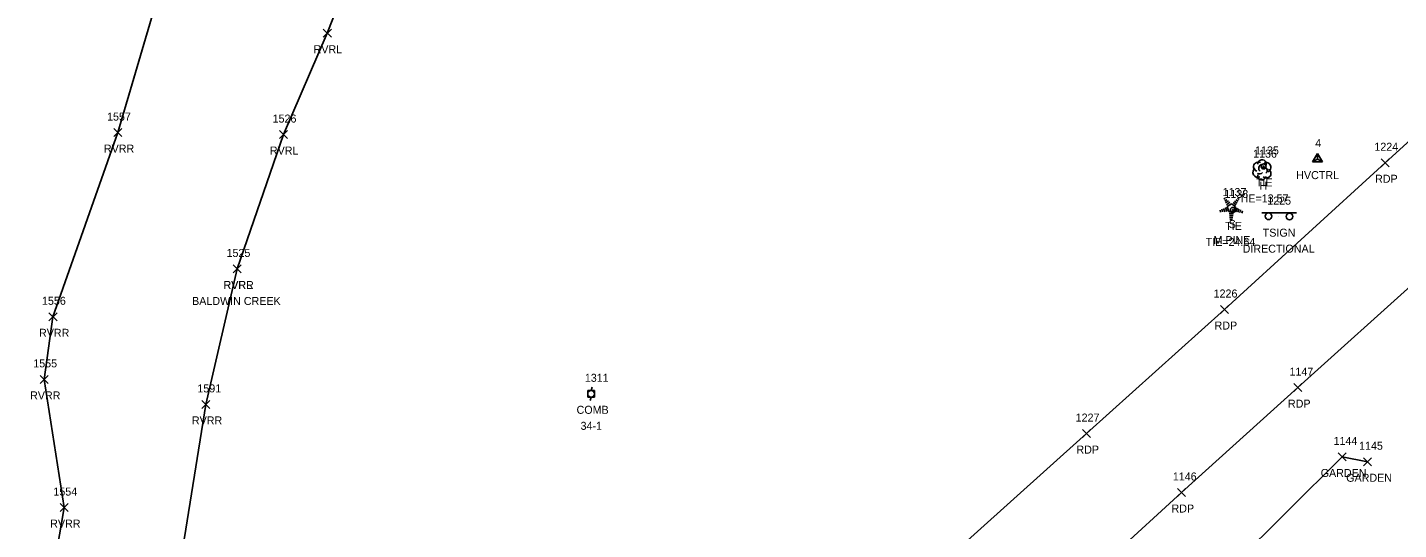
# Model space of a CAD drawing. Extents: x 1496556 to 1498241, y 599216 to 604470.
# Drawn here: x 1497204.8 to 1497547.4, y 603168.8 to 603294.3 of the extents above; entities that cross this region are included whole.
import ezdxf

# ---------------------------------------------------------------- set-up
doc = ezdxf.new("R2010")
doc.units = 0
for name, color, linetype in [('C_A', 7, 'Continuous'), ('C_C', 7, 'Continuous'), ('C_I', 7, 'Continuous'), ('CBP', 7, 'Continuous'), ('CPSM', 7, 'Continuous'), ('L_A', 7, 'Continuous'), ('L_C', 7, 'Continuous'), ('L_I', 7, 'Continuous'), ('L_TIC', 7, 'Continuous'), ('LAPB', 7, 'Continuous'), ('LAWE', 7, 'Continuous'), ('LTC', 7, 'Continuous'), ('LTD', 7, 'Continuous'), ('P_A', 7, 'Continuous'), ('P_I', 7, 'Continuous'), ('P_TIC', 7, 'Continuous'), ('PET', 7, 'Continuous'), ('S_A', 7, 'Continuous'), ('S_C', 7, 'Continuous'), ('S_I', 7, 'Continuous'), ('SSGN', 7, 'Continuous'), ('U_A', 7, 'Continuous'), ('U_C', 7, 'Continuous'), ('U_I', 7, 'Continuous'), ('UP', 7, 'Continuous')]:
    doc.layers.add(name, color=color, linetype=linetype)

msp = doc.modelspace()

# ---------------------------------------------------------------- linework, layer by layer
at = {"layer": 'CBP'}
for centre, radius in [((1497513.71, 603259.59), 0.625), ((1497513.71, 603259.59), 0.0833), ((1497506.03, 603248.72), 0.625), ((1497506.03, 603248.72), 0.0833)]:
    msp.add_circle(centre, radius, dxfattribs=at)
at = {"layer": 'CPSM'}
for p, q in [((1497525.91, 603260.69), (1497527.16, 603262.85)), ((1497525.91, 603260.69), (1497527.16, 603261.41)), ((1497528.41, 603260.69), (1497527.16, 603262.85)), ((1497527.16, 603261.41), (1497527.16, 603262.85)), ((1497527.16, 603261.41), (1497527.16, 603261.41)), ((1497527.16, 603261.41), (1497528.41, 603260.69)), ((1497525.91, 603260.69), (1497528.41, 603260.69))]:
    msp.add_line(p, q, dxfattribs=at)
at = {"layer": 'L_TIC'}
for points in [[(1497278.78, 603291.86), (1497280.78, 603293.86)], [(1497280.78, 603291.86), (1497278.78, 603293.86)], [(1497226.45, 603267.03), (1497228.45, 603269.03)], [(1497228.45, 603267.03), (1497226.45, 603269.03)], [(1497267.86, 603266.54), (1497269.86, 603268.54)], [(1497269.86, 603266.54), (1497267.86, 603268.54)], [(1497256.29, 603232.96), (1497258.29, 603234.96)], [(1497258.29, 603232.96), (1497256.29, 603234.96)], [(1497256.29, 603232.96), (1497258.29, 603234.96)], [(1497258.29, 603232.96), (1497256.29, 603234.96)], [(1497210.24, 603221.01), (1497212.24, 603223.01)], [(1497212.24, 603221.01), (1497210.24, 603223.01)], [(1497208.01, 603205.37), (1497210.01, 603207.37)], [(1497210.01, 603205.37), (1497208.01, 603207.37)], [(1497248.44, 603199.12), (1497250.44, 603201.12)], [(1497250.44, 603199.12), (1497248.44, 603201.12)], [(1497532.3, 603185.99), (1497534.3, 603187.99)], [(1497534.3, 603185.99), (1497532.3, 603187.99)], [(1497538.67, 603184.79), (1497540.67, 603186.79)], [(1497540.67, 603184.79), (1497538.67, 603186.79)], [(1497213.03, 603173.34), (1497215.03, 603175.34)], [(1497215.03, 603173.34), (1497213.03, 603175.34)]]:
    msp.add_lwpolyline(points, dxfattribs=at)
at = {"layer": 'LAPB'}
msp.add_lwpolyline([(1497506.31, 603145.06), (1497502.6, 603154.88), (1497506.17, 603160.03), (1497533.3, 603186.99), (1497539.67, 603185.79)], dxfattribs=at)
at = {"layer": 'LAWE'}
for points in [[(1497189.81, 603091.49), (1497191.67, 603112.98), (1497209.98, 603150.46), (1497214.03, 603174.34), (1497209.01, 603206.37), (1497211.24, 603222.01), (1497227.45, 603268.03), (1497246.38, 603332.34), (1497269.89, 603360.04), (1497296.95, 603397.6), (1497313.57, 603422.44), (1497323.64, 603438.94), (1497334.8, 603445.38), (1497344.77, 603450.19), (1497370.1, 603467.8), (1497419.49, 603471.31), (1497456.04, 603468.84), (1497488.04, 603460.85), (1497518.38, 603461.84), (1497564.45, 603467.31)], [(1497257.29, 603233.96), (1497268.86, 603267.54), (1497279.78, 603292.86), (1497288.82, 603315.96), (1497298.59, 603335.95), (1497306.16, 603346.61), (1497313.39, 603358.86), (1497323.23, 603375.14), (1497334.35, 603385.12), (1497348.33, 603402.71), (1497361.35, 603417.11), (1497378.91, 603425.6), (1497400.91, 603427.88), (1497444.15, 603428.7), (1497481.24, 603420.82), (1497519.31, 603418.69), (1497550.81, 603423.71)], [(1497257.29, 603233.96), (1497249.44, 603200.12), (1497237.58, 603126.42), (1497229.71, 603101.35), (1497207.4, 603061.16)]]:
    msp.add_lwpolyline(points, dxfattribs=at)
at = {"layer": 'LTC'}
for p, q in [((1497503.78, 603251.38), (1497504.13, 603251.64)), ((1497503.98, 603250.92), (1497504.51, 603251.3)), ((1497504.19, 603250.45), (1497504.9, 603250.96)), ((1497506.43, 603250.93), (1497507.11, 603250.43)), ((1497506.8, 603251.27), (1497507.35, 603250.87)), ((1497507.17, 603251.62), (1497507.59, 603251.32)), ((1497502.81, 603248.66), (1497502.96, 603248.19)), ((1497503.26, 603248.88), (1497503.47, 603248.23)), ((1497503.72, 603249.09), (1497503.99, 603248.26)), ((1497504.17, 603249.31), (1497504.5, 603248.29)), ((1497504.4, 603249.98), (1497505.28, 603250.62)), ((1497504.63, 603249.53), (1497505.64, 603250.26)), ((1497504.63, 603249.53), (1497505.02, 603248.34)), ((1497506.25, 603248.34), (1497505.02, 603248.34)), ((1497506.21, 603247.84), (1497505.06, 603247.84)), ((1497506.12, 603247.34), (1497505.14, 603247.34)), ((1497505.64, 603250.26), (1497506.64, 603249.54)), ((1497506.06, 603250.58), (1497506.87, 603249.99)), ((1497506.64, 603249.54), (1497506.25, 603248.34)), ((1497507.07, 603249.27), (1497506.74, 603248.23)), ((1497507.52, 603249.02), (1497507.23, 603248.13)), ((1497507.96, 603248.77), (1497507.73, 603248.04)), ((1497508.41, 603248.52), (1497508.22, 603247.94)), ((1497506.04, 603246.84), (1497505.21, 603246.84)), ((1497505.96, 603246.34), (1497505.28, 603246.34))]:
    msp.add_line(p, q, dxfattribs=at)
at = {"layer": 'LTD'}
msp.add_line((1497513.26, 603258.77), (1497513.26, 603258.77), dxfattribs=at)
msp.add_line((1497513.26, 603258.77), (1497513.26, 603258.77), dxfattribs=at)
msp.add_arc((1497513.3, 603260.2), 1.05, 335.5272, 180.9563, dxfattribs=at)
for centre, major_axis, ratio, start_param, end_param in [((1497512.17, 603258.06), (0.58, -1.04), 0.959034, 3.141593, 6.283185), ((1497512.47, 603259.44), (1.21, -0.51), 0.895232, 1.570796, 4.712389), ((1497512.8, 603258.02), (-0.625, -0.083), 0.423636, 0, 3.141593), ((1497513.05, 603259.23), (-0.208, -0.792), 0.645439, 3.141593, 6.283185), ((1497513.76, 603258.6), (-0.5, 0.667), 0.989748, 3.141593, 6.283185), ((1497514.26, 603257.94), (-1.09, 0.79), 0.841452, 1.570796, 4.712389), ((1497514.3, 603259.35), (-1.14, -0.48), 0.949671, 1.570796, 4.712389), ((1497513.26, 603257.27), (0.26, 1.06), 0.942809, 1.570796, 4.712389)]:
    msp.add_ellipse(centre, major_axis=major_axis, ratio=ratio, start_param=start_param, end_param=end_param, dxfattribs=at)
at = {"layer": 'P_TIC'}
for points in [[(1497543.07, 603259.5), (1497545.07, 603261.5)], [(1497545.07, 603259.5), (1497543.07, 603261.5)], [(1497502.96, 603222.83), (1497504.96, 603224.83)], [(1497504.96, 603222.83), (1497502.96, 603224.83)], [(1497521.29, 603203.31), (1497523.29, 603205.31)], [(1497523.29, 603203.31), (1497521.29, 603205.31)], [(1497468.44, 603191.83), (1497470.44, 603193.83)], [(1497470.44, 603191.83), (1497468.44, 603193.83)], [(1497492.2, 603177.11), (1497494.2, 603179.11)], [(1497494.2, 603177.11), (1497492.2, 603179.11)]]:
    msp.add_lwpolyline(points, dxfattribs=at)
at = {"layer": 'PET'}
for points in [[(1497580.33, 603293.36), (1497544.07, 603260.5), (1497503.96, 603223.83), (1497469.44, 603192.83), (1497432.27, 603159.48), (1497398.1, 603128.8), (1497361.66, 603094.11), (1497332.15, 603067.83), (1497309.09, 603046.17), (1497294.72, 603034.46), (1497285.78, 603029.77), (1497276.79, 603028.23), (1497267.28, 603029.35), (1497255.38, 603035.01), (1497245.34, 603044.47)], [(1497277.08, 602932.51), (1497278.76, 602955.27), (1497283.83, 602972.38), (1497292.85, 602989.5), (1497302.51, 603001.53), (1497319.84, 603019.72), (1497338.13, 603037.05), (1497360.02, 603057.19), (1497386.8, 603081.38), (1497411.61, 603104.29), (1497436.99, 603126.72), (1497459.34, 603147.15), (1497493.2, 603178.11), (1497522.29, 603204.31), (1497552.95, 603231.97)]]:
    msp.add_lwpolyline(points, dxfattribs=at)
at = {"layer": 'SSGN'}
for p, q in [((1497513.28, 603247.95), (1497521.88, 603247.95)), ((1497517.3, 603247.05), (1497517.3, 603247.05))]:
    msp.add_line(p, q, dxfattribs=at)
for centre in [(1497514.94, 603247.12), (1497520.16, 603247.05)]:
    msp.add_circle(centre, 0.833, dxfattribs=at)
at = {"layer": 'UP'}
for p, q in [((1497344.83, 603201.94), (1497344.83, 603203.61)), ((1497344.83, 603203.61), (1497346.5, 603203.61)), ((1497345.92, 603204.44), (1497345.67, 603203.61)), ((1497346.5, 603203.61), (1497346.5, 603201.94)), ((1497346.5, 603201.94), (1497344.83, 603201.94)), ((1497345.42, 603201.11), (1497345.67, 603201.94)), ((1497345.67, 603202.77), (1497345.67, 603202.77))]:
    msp.add_line(p, q, dxfattribs=at)
msp.add_circle((1497345.67, 603202.77), 0.833, dxfattribs=at)

# ---------------------------------------------------------------- texts
at = {"layer": 'C_A'}
for s, p in [('HVCTRL', (1497521.85, 603256.41)), ('TIE', (1497511.79, 603254.59)), ('TIE', (1497504.11, 603243.72))]:
    msp.add_text(s, height=2, dxfattribs=at).set_placement(p)
at = {"layer": 'C_C'}
for s, p in [('TIE=13.57', (1497507.5, 603250.59)), ('TIE=24.64', (1497499.22, 603239.72))]:
    msp.add_text(s, height=2, dxfattribs=at).set_placement(p)
at = {"layer": 'C_I'}
for s, p in [('1135', (1497511.58, 603262.59)), ('4', (1497526.59, 603264.41)), ('1138', (1497503.91, 603251.72))]:
    msp.add_text(s, height=2, dxfattribs=at).set_placement(p)
at = {"layer": 'L_A'}
for s, p in [('RVRL', (1497276.35, 603287.86)), ('RVRR', (1497223.96, 603263.03)), ('RVRL', (1497265.43, 603262.54)), ('H', (1497512.69, 603253.77)), ('S', (1497504.97, 603244.17)), ('RVRR', (1497253.81, 603228.96)), ('RVRL', (1497253.86, 603228.96)), ('RVRR', (1497207.75, 603217.01)), ('RVRR', (1497205.52, 603201.37)), ('RVRR', (1497245.95, 603195.12)), ('GARDEN', (1497527.97, 603181.99)), ('GARDEN', (1497534.34, 603180.79)), ('RVRR', (1497210.54, 603169.34))]:
    msp.add_text(s, height=2, dxfattribs=at).set_placement(p)
at = {"layer": 'L_C'}
for s, p in [('M.PINE', (1497501.19, 603240.17)), ('BALDWIN CREEK', (1497245.99, 603224.96))]:
    msp.add_text(s, height=2, dxfattribs=at).set_placement(p)
at = {"layer": 'L_I'}
for s, p in [('1557', (1497224.75, 603271.03)), ('1526', (1497266.11, 603270.54)), ('1136', (1497511.08, 603261.77)), ('1137', (1497503.45, 603252.17)), ('1525', (1497254.6, 603236.96)), ('1525', (1497254.6, 603236.96)), ('1556', (1497208.49, 603225.01)), ('1555', (1497206.31, 603209.37)), ('1591', (1497247.31, 603203.12)), ('1144', (1497531.17, 603189.99)), ('1145', (1497537.55, 603188.79)), ('1554', (1497211.34, 603177.34))]:
    msp.add_text(s, height=2, dxfattribs=at).set_placement(p)
at = {"layer": 'LTC'}
msp.add_text('.', height=1.04, rotation=270, dxfattribs=at).set_placement((1497505.52, 603249.28))
at = {"layer": 'P_A'}
for p in [(1497541.55, 603255.5), (1497501.45, 603218.83), (1497519.78, 603199.31), (1497466.93, 603187.83), (1497490.69, 603173.11)]:
    msp.add_text('RDP', height=2, dxfattribs=at).set_placement(p)
at = {"layer": 'P_I'}
for s, p in [('1224', (1497541.37, 603263.5)), ('1226', (1497501.21, 603226.83)), ('1147', (1497520.17, 603207.31)), ('1227', (1497466.74, 603195.83)), ('1146', (1497491.02, 603181.11))]:
    msp.add_text(s, height=2, dxfattribs=at).set_placement(p)
at = {"layer": 'S_A'}
msp.add_text('TSIGN', height=2, dxfattribs=at).set_placement((1497513.48, 603242.03))
at = {"layer": 'S_C'}
msp.add_text('DIRECTIONAL', height=2, dxfattribs=at).set_placement((1497508.46, 603238.03))
at = {"layer": 'S_I'}
msp.add_text('1225', height=2, dxfattribs=at).set_placement((1497514.61, 603250.03))
at = {"layer": 'U_A'}
msp.add_text('COMB', height=2, dxfattribs=at).set_placement((1497342.05, 603197.77))
at = {"layer": 'U_C'}
msp.add_text('34-1', height=2, dxfattribs=at).set_placement((1497343.05, 603193.77))
at = {"layer": 'U_I'}
msp.add_text('1311', height=2, dxfattribs=at).set_placement((1497344.11, 603205.77))

doc.saveas('drawing.dxf')
